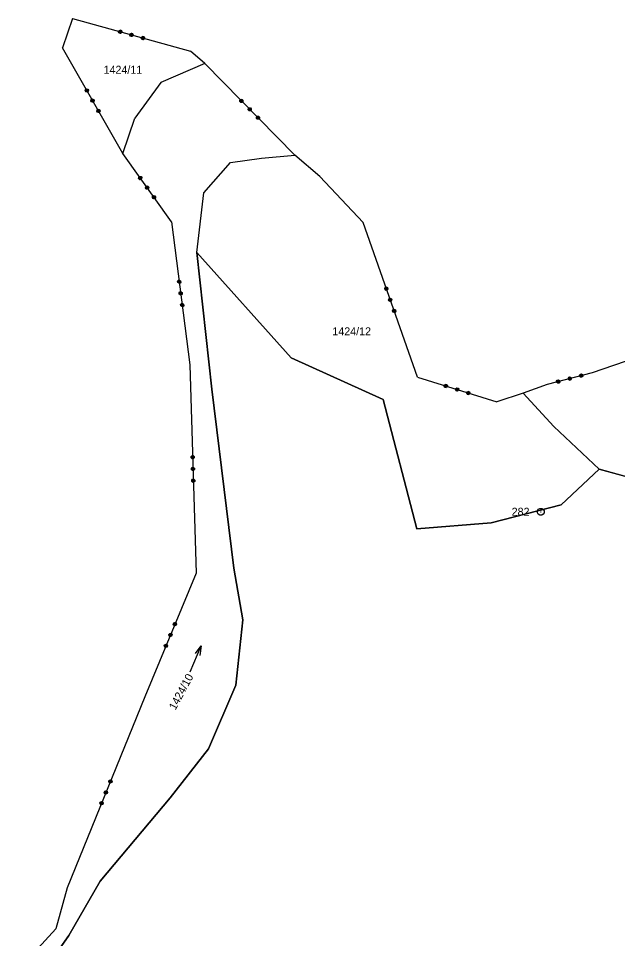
# Model space of a CAD drawing. Extents: x -779618 to -776429, y -1144546 to -1143350.
# Drawn here: x -779433.1 to -779305.8, y -1143589.4 to -1143393.9 of the extents above; entities that cross this region are included whole.
import ezdxf

# ---------------------------------------------------------------- set-up
doc = ezdxf.new("R2010")
doc.units = 0
for name, color, linetype in [('1', 7, 'Continuous'), ('11', 7, 'Continuous'), ('2', 7, 'Continuous'), ('3', 7, 'Continuous'), ('8', 7, 'Continuous')]:
    doc.layers.add(name, color=color, linetype=linetype)

msp = doc.modelspace()

# ---------------------------------------------------------------- linework, layer by layer
at = {"layer": '1'}
for p, q in [((-779421.62, -1143393.89), (-779423.77, -1143400.14)), ((-779421.62, -1143393.89), (-779396.57, -1143400.88)), ((-779410.98, -1143422.6), (-779423.77, -1143400.14)), ((-779393.56, -1143403.48), (-779396.57, -1143400.88)), ((-779393.56, -1143403.48), (-779402.9, -1143407.52)), ((-779393.56, -1143403.48), (-779374.42, -1143422.93)), ((-779402.9, -1143407.52), (-779408.4, -1143415.09)), ((-779410.98, -1143422.6), (-779408.4, -1143415.09)), ((-779400.61, -1143437.08), (-779410.98, -1143422.6)), ((-779381.5, -1143423.6), (-779374.42, -1143422.93)), ((-779369.08, -1143427.47), (-779374.42, -1143422.93)), ((-779393.75, -1143430.93), (-779388.05, -1143424.48)), ((-779388.05, -1143424.48), (-779381.5, -1143423.6)), ((-779359.9, -1143437.25), (-779369.08, -1143427.47)), ((-779395.24, -1143443.6), (-779393.75, -1143430.93)), ((-779400.61, -1143437.08), (-779396.69, -1143467.5)), ((-779348.37, -1143470.11), (-779359.9, -1143437.25)), ((-779375.19, -1143466.02), (-779395.24, -1143443.6)), ((-779395.24, -1143443.6), (-779392.06, -1143472.65)), ((-779396.69, -1143467.5), (-779395.39, -1143511.72)), ((-779355.63, -1143474.84), (-779375.19, -1143466.02)), ((-779301.92, -1143466.01), (-779311.23, -1143469.16)), ((-779311.23, -1143469.16), (-779320.76, -1143471.66)), ((-779348.37, -1143470.11), (-779331.49, -1143475.33)), ((-779320.76, -1143471.66), (-779325.89, -1143473.5)), ((-779392.06, -1143472.65), (-779387.33, -1143510.67)), ((-779325.89, -1143473.5), (-779331.49, -1143475.33)), ((-779319.39, -1143480.62), (-779325.89, -1143473.5)), ((-779348.5, -1143502.34), (-779355.63, -1143474.84)), ((-779309.71, -1143489.68), (-779319.39, -1143480.62)), ((-779309.71, -1143489.68), (-779317.8, -1143497.23)), ((-779287.14, -1143495.83), (-779309.71, -1143489.68)), ((-779317.8, -1143497.23), (-779332.68, -1143501.03)), ((-779332.68, -1143501.03), (-779348.5, -1143502.34)), ((-779387.33, -1143510.67), (-779385.43, -1143521.63)), ((-779395.39, -1143511.72), (-779406.26, -1143538.03)), ((-779385.43, -1143521.63), (-779386.97, -1143535.53)), ((-779386.97, -1143535.53), (-779392.76, -1143549.06)), ((-779406.26, -1143538.03), (-779422.8, -1143578.6)), ((-779392.76, -1143549.06), (-779400.9, -1143559.45)), ((-779400.9, -1143559.45), (-779415.75, -1143577.19)), ((-779415.75, -1143577.19), (-779422.4, -1143588.74)), ((-779422.8, -1143578.6), (-779425.2, -1143587.3)), ((-779425.2, -1143587.3), (-779441.4, -1143604.95)), ((-779422.4, -1143588.74), (-779431.16, -1143601.12))]:
    msp.add_line(p, q, dxfattribs=at)
for points in [[(-779411.29, -1143396.44), (-779411.16, -1143396.67), (-779411.23, -1143396.93), (-779411.47, -1143397.07), (-779411.73, -1143396.99), (-779411.86, -1143396.76), (-779411.79, -1143396.5), (-779411.55, -1143396.37), (-779411.29, -1143396.44), (-779411.29, -1143396.48), (-779411.52, -1143396.42), (-779411.62, -1143396.47), (-779411.24, -1143396.58), (-779411.2, -1143396.67), (-779411.72, -1143396.53), (-779411.74, -1143396.6), (-779411.23, -1143396.75), (-779411.24, -1143396.83), (-779411.75, -1143396.68), (-779411.78, -1143396.76), (-779411.27, -1143396.9), (-779411.34, -1143396.97), (-779411.75, -1143396.85), (-779411.7, -1143396.95), (-779411.43, -1143397.02)], [(-779408.87, -1143397.11), (-779408.74, -1143397.35), (-779408.81, -1143397.61), (-779409.05, -1143397.74), (-779409.31, -1143397.67), (-779409.44, -1143397.43), (-779409.37, -1143397.17), (-779409.13, -1143397.04), (-779408.87, -1143397.11), (-779408.89, -1143397.15), (-779409.13, -1143397.09), (-779409.22, -1143397.14), (-779408.84, -1143397.25), (-779408.78, -1143397.35), (-779409.32, -1143397.2), (-779409.34, -1143397.27), (-779408.8, -1143397.42), (-779408.83, -1143397.5), (-779409.37, -1143397.35), (-779409.39, -1143397.43), (-779408.85, -1143397.58), (-779408.95, -1143397.63), (-779409.33, -1143397.53), (-779409.28, -1143397.63), (-779409.05, -1143397.69)], [(-779406.46, -1143397.79), (-779406.32, -1143398.02), (-779406.4, -1143398.28), (-779406.63, -1143398.42), (-779406.89, -1143398.34), (-779407.02, -1143398.11), (-779406.95, -1143397.85), (-779406.72, -1143397.72), (-779406.46, -1143397.79), (-779406.51, -1143397.82), (-779406.74, -1143397.75), (-779406.82, -1143397.81), (-779406.45, -1143397.92), (-779406.39, -1143398.01), (-779406.9, -1143397.87), (-779406.92, -1143397.95), (-779406.42, -1143398.09), (-779406.44, -1143398.17), (-779406.94, -1143398.03), (-779406.97, -1143398.1), (-779406.47, -1143398.24), (-779406.53, -1143398.31), (-779406.92, -1143398.2), (-779406.9, -1143398.29), (-779406.67, -1143398.35)], [(-779418.96, -1143409.22), (-779418.89, -1143408.97), (-779418.66, -1143408.83), (-779418.4, -1143408.9), (-779418.26, -1143409.14), (-779418.34, -1143409.4), (-779418.57, -1143409.53), (-779418.83, -1143409.46), (-779418.96, -1143409.22), (-779418.91, -1143409.24), (-779418.79, -1143409.45), (-779418.69, -1143409.46), (-779418.88, -1143409.13), (-779418.85, -1143409.02), (-779418.59, -1143409.47), (-779418.52, -1143409.43), (-779418.78, -1143408.98), (-779418.71, -1143408.94), (-779418.45, -1143409.39), (-779418.38, -1143409.36), (-779418.64, -1143408.91), (-779418.55, -1143408.91), (-779418.34, -1143409.26), (-779418.3, -1143409.18), (-779418.42, -1143408.97)], [(-779417.72, -1143411.41), (-779417.65, -1143411.15), (-779417.42, -1143411.01), (-779417.16, -1143411.09), (-779417.02, -1143411.32), (-779417.1, -1143411.58), (-779417.33, -1143411.71), (-779417.59, -1143411.64), (-779417.72, -1143411.41), (-779417.68, -1143411.4), (-779417.56, -1143411.6), (-779417.45, -1143411.63), (-779417.65, -1143411.29), (-779417.62, -1143411.18), (-779417.35, -1143411.66), (-779417.28, -1143411.62), (-779417.55, -1143411.14), (-779417.48, -1143411.1), (-779417.21, -1143411.58), (-779417.14, -1143411.55), (-779417.41, -1143411.06), (-779417.3, -1143411.09), (-779417.11, -1143411.44), (-779417.08, -1143411.33), (-779417.2, -1143411.12)], [(-779385.42, -1143411.29), (-779385.43, -1143411.56), (-779385.62, -1143411.75), (-779385.89, -1143411.75), (-779386.08, -1143411.56), (-779386.08, -1143411.29), (-779385.88, -1143411.1), (-779385.61, -1143411.1), (-779385.42, -1143411.29), (-779385.45, -1143411.33), (-779385.61, -1143411.16), (-779385.73, -1143411.15), (-779385.45, -1143411.44), (-779385.46, -1143411.54), (-779385.84, -1143411.15), (-779385.9, -1143411.21), (-779385.53, -1143411.59), (-779385.58, -1143411.65), (-779385.95, -1143411.27), (-779386, -1143411.33), (-779385.63, -1143411.71), (-779385.73, -1143411.73), (-779386.03, -1143411.42), (-779386.03, -1143411.53), (-779385.84, -1143411.73)], [(-779383.66, -1143413.08), (-779383.67, -1143413.35), (-779383.86, -1143413.54), (-779384.13, -1143413.54), (-779384.32, -1143413.34), (-779384.31, -1143413.08), (-779384.12, -1143412.89), (-779383.85, -1143412.89), (-779383.66, -1143413.08), (-779383.7, -1143413.1), (-779383.87, -1143412.93), (-779383.98, -1143412.93), (-779383.7, -1143413.21), (-779383.7, -1143413.33), (-779384.09, -1143412.93), (-779384.15, -1143412.98), (-779383.76, -1143413.38), (-779383.82, -1143413.44), (-779384.21, -1143413.04), (-779384.26, -1143413.1), (-779383.87, -1143413.5), (-779383.99, -1143413.49), (-779384.27, -1143413.21), (-779384.27, -1143413.32), (-779384.1, -1143413.49)], [(-779416.48, -1143413.59), (-779416.41, -1143413.33), (-779416.18, -1143413.2), (-779415.92, -1143413.27), (-779415.78, -1143413.5), (-779415.85, -1143413.76), (-779416.09, -1143413.89), (-779416.35, -1143413.82), (-779416.48, -1143413.59), (-779416.45, -1143413.56), (-779416.33, -1143413.77), (-779416.22, -1143413.8), (-779416.42, -1143413.45), (-779416.38, -1143413.36), (-779416.11, -1143413.83), (-779416.05, -1143413.79), (-779416.31, -1143413.33), (-779416.24, -1143413.28), (-779415.98, -1143413.74), (-779415.91, -1143413.7), (-779416.17, -1143413.24), (-779416.08, -1143413.24), (-779415.87, -1143413.62), (-779415.83, -1143413.52), (-779415.97, -1143413.27)], [(-779381.9, -1143414.87), (-779381.9, -1143415.14), (-779382.1, -1143415.33), (-779382.37, -1143415.32), (-779382.56, -1143415.13), (-779382.55, -1143414.86), (-779382.36, -1143414.67), (-779382.09, -1143414.68), (-779381.9, -1143414.87), (-779381.96, -1143414.87), (-779382.13, -1143414.7), (-779382.23, -1143414.71), (-779381.96, -1143414.98), (-779381.96, -1143415.09), (-779382.33, -1143414.72), (-779382.38, -1143414.78), (-779382.02, -1143415.15), (-779382.08, -1143415.21), (-779382.44, -1143414.84), (-779382.5, -1143414.89), (-779382.14, -1143415.26), (-779382.22, -1143415.28), (-779382.51, -1143414.99), (-779382.53, -1143415.08), (-779382.37, -1143415.25)], [(-779407.6, -1143427.87), (-779407.55, -1143427.61), (-779407.33, -1143427.45), (-779407.07, -1143427.49), (-779406.91, -1143427.71), (-779406.96, -1143427.98), (-779407.18, -1143428.13), (-779407.44, -1143428.09), (-779407.6, -1143427.87), (-779407.54, -1143427.88), (-779407.4, -1143428.08), (-779407.3, -1143428.08), (-779407.52, -1143427.77), (-779407.5, -1143427.66), (-779407.2, -1143428.08), (-779407.14, -1143428.03), (-779407.44, -1143427.61), (-779407.37, -1143427.56), (-779407.07, -1143427.99), (-779407, -1143427.95), (-779407.3, -1143427.53), (-779407.22, -1143427.51), (-779406.98, -1143427.85), (-779406.94, -1143427.76), (-779407.08, -1143427.56)], [(-779406.14, -1143429.91), (-779406.09, -1143429.65), (-779405.87, -1143429.49), (-779405.61, -1143429.53), (-779405.45, -1143429.75), (-779405.49, -1143430.02), (-779405.71, -1143430.18), (-779405.98, -1143430.13), (-779406.14, -1143429.91), (-779406.1, -1143429.9), (-779405.96, -1143430.09), (-779405.85, -1143430.11), (-779406.08, -1143429.79), (-779406.06, -1143429.67), (-779405.74, -1143430.13), (-779405.67, -1143430.08), (-779406, -1143429.63), (-779405.93, -1143429.58), (-779405.61, -1143430.04), (-779405.54, -1143429.99), (-779405.87, -1143429.53), (-779405.75, -1143429.55), (-779405.52, -1143429.88), (-779405.5, -1143429.77), (-779405.64, -1143429.57)], [(-779404.68, -1143431.95), (-779404.63, -1143431.69), (-779404.41, -1143431.53), (-779404.15, -1143431.58), (-779403.99, -1143431.79), (-779404.03, -1143432.06), (-779404.25, -1143432.22), (-779404.52, -1143432.17), (-779404.68, -1143431.95), (-779404.65, -1143431.92), (-779404.51, -1143432.12), (-779404.4, -1143432.14), (-779404.63, -1143431.81), (-779404.6, -1143431.72), (-779404.29, -1143432.15), (-779404.22, -1143432.11), (-779404.53, -1143431.68), (-779404.47, -1143431.62), (-779404.16, -1143432.05), (-779404.1, -1143432.01), (-779404.41, -1143431.58), (-779404.31, -1143431.57), (-779404.06, -1143431.92), (-779404.04, -1143431.82), (-779404.2, -1143431.59)], [(-779398.64, -1143449.9), (-779398.8, -1143450.11), (-779399.07, -1143450.15), (-779399.28, -1143449.98), (-779399.32, -1143449.71), (-779399.15, -1143449.5), (-779398.88, -1143449.47), (-779398.67, -1143449.63), (-779398.64, -1143449.9), (-779398.67, -1143449.91), (-779398.71, -1143449.68), (-779398.8, -1143449.61), (-779398.74, -1143450), (-779398.82, -1143450.07), (-779398.88, -1143449.54), (-779398.96, -1143449.55), (-779398.9, -1143450.07), (-779398.97, -1143450.09), (-779399.04, -1143449.57), (-779399.12, -1143449.58), (-779399.05, -1143450.1), (-779399.14, -1143450.06), (-779399.19, -1143449.64), (-779399.27, -1143449.72), (-779399.23, -1143450)], [(-779398.31, -1143452.39), (-779398.48, -1143452.6), (-779398.75, -1143452.64), (-779398.96, -1143452.47), (-779398.99, -1143452.2), (-779398.83, -1143451.99), (-779398.56, -1143451.96), (-779398.35, -1143452.12), (-779398.31, -1143452.39), (-779398.36, -1143452.38), (-779398.39, -1143452.14), (-779398.48, -1143452.08), (-779398.42, -1143452.47), (-779398.49, -1143452.56), (-779398.57, -1143452.01), (-779398.64, -1143452.02), (-779398.57, -1143452.57), (-779398.65, -1143452.58), (-779398.72, -1143452.03), (-779398.8, -1143452.04), (-779398.73, -1143452.59), (-779398.82, -1143452.52), (-779398.87, -1143452.13), (-779398.94, -1143452.22), (-779398.91, -1143452.45)], [(-779355.31, -1143451.29), (-779355.2, -1143451.04), (-779354.94, -1143450.95), (-779354.7, -1143451.07), (-779354.61, -1143451.32), (-779354.73, -1143451.57), (-779354.98, -1143451.66), (-779355.22, -1143451.54), (-779355.31, -1143451.29), (-779355.26, -1143451.31), (-779355.18, -1143451.54), (-779355.09, -1143451.57), (-779355.21, -1143451.21), (-779355.16, -1143451.11), (-779354.99, -1143451.6), (-779354.92, -1143451.57), (-779355.09, -1143451.08), (-779355.01, -1143451.05), (-779354.84, -1143451.54), (-779354.76, -1143451.53), (-779354.93, -1143451.04), (-779354.85, -1143451.05), (-779354.71, -1143451.43), (-779354.65, -1143451.36), (-779354.73, -1143451.13)], [(-779354.48, -1143453.65), (-779354.37, -1143453.41), (-779354.11, -1143453.32), (-779353.87, -1143453.44), (-779353.78, -1143453.69), (-779353.9, -1143453.94), (-779354.15, -1143454.02), (-779354.39, -1143453.91), (-779354.48, -1143453.65), (-779354.44, -1143453.65), (-779354.36, -1143453.88), (-779354.26, -1143453.93), (-779354.39, -1143453.55), (-779354.34, -1143453.45), (-779354.16, -1143453.97), (-779354.08, -1143453.95), (-779354.27, -1143453.42), (-779354.19, -1143453.39), (-779354.01, -1143453.92), (-779353.93, -1143453.9), (-779354.12, -1143453.37), (-779354.02, -1143453.42), (-779353.88, -1143453.79), (-779353.83, -1143453.69), (-779353.91, -1143453.46)], [(-779397.99, -1143454.88), (-779398.16, -1143455.09), (-779398.42, -1143455.12), (-779398.64, -1143454.96), (-779398.67, -1143454.69), (-779398.51, -1143454.48), (-779398.24, -1143454.45), (-779398.03, -1143454.61), (-779397.99, -1143454.88), (-779398.04, -1143454.84), (-779398.07, -1143454.6), (-779398.16, -1143454.56), (-779398.11, -1143454.93), (-779398.18, -1143455.02), (-779398.24, -1143454.51), (-779398.32, -1143454.52), (-779398.26, -1143455.03), (-779398.33, -1143455.04), (-779398.4, -1143454.53), (-779398.48, -1143454.53), (-779398.42, -1143455.04), (-779398.5, -1143455.01), (-779398.55, -1143454.61), (-779398.63, -1143454.67), (-779398.59, -1143454.9)], [(-779353.65, -1143456.02), (-779353.54, -1143455.78), (-779353.28, -1143455.69), (-779353.04, -1143455.81), (-779352.95, -1143456.06), (-779353.07, -1143456.3), (-779353.32, -1143456.39), (-779353.56, -1143456.28), (-779353.65, -1143456.02), (-779353.62, -1143456), (-779353.54, -1143456.23), (-779353.44, -1143456.28), (-779353.57, -1143455.9), (-779353.51, -1143455.81), (-779353.34, -1143456.32), (-779353.26, -1143456.3), (-779353.43, -1143455.8), (-779353.36, -1143455.76), (-779353.19, -1143456.26), (-779353.11, -1143456.24), (-779353.29, -1143455.74), (-779353.2, -1143455.76), (-779353.05, -1143456.16), (-779353, -1143456.07), (-779353.09, -1143455.81)], [(-779313.62, -1143470.12), (-779313.85, -1143469.98), (-779313.92, -1143469.72), (-779313.79, -1143469.49), (-779313.52, -1143469.42), (-779313.29, -1143469.56), (-779313.22, -1143469.82), (-779313.36, -1143470.05), (-779313.62, -1143470.12), (-779313.64, -1143470.08), (-779313.41, -1143470.02), (-779313.35, -1143469.92), (-779313.74, -1143470.03), (-779313.82, -1143469.96), (-779313.29, -1143469.83), (-779313.32, -1143469.75), (-779313.83, -1143469.88), (-779313.86, -1143469.81), (-779313.35, -1143469.67), (-779313.37, -1143469.6), (-779313.88, -1143469.73), (-779313.85, -1143469.64), (-779313.43, -1143469.53), (-779313.52, -1143469.47), (-779313.79, -1143469.54)], [(-779342.1, -1143471.71), (-779341.97, -1143471.95), (-779342.05, -1143472.21), (-779342.29, -1143472.33), (-779342.55, -1143472.25), (-779342.67, -1143472.02), (-779342.6, -1143471.76), (-779342.36, -1143471.63), (-779342.1, -1143471.71), (-779342.1, -1143471.75), (-779342.33, -1143471.68), (-779342.43, -1143471.74), (-779342.05, -1143471.85), (-779342.02, -1143471.95), (-779342.53, -1143471.79), (-779342.55, -1143471.87), (-779342.05, -1143472.02), (-779342.06, -1143472.1), (-779342.57, -1143471.95), (-779342.59, -1143472.02), (-779342.09, -1143472.18), (-779342.16, -1143472.24), (-779342.57, -1143472.11), (-779342.53, -1143472.21), (-779342.26, -1143472.29)], [(-779318.48, -1143471.39), (-779318.71, -1143471.26), (-779318.78, -1143470.99), (-779318.64, -1143470.76), (-779318.38, -1143470.69), (-779318.15, -1143470.83), (-779318.08, -1143471.09), (-779318.22, -1143471.32), (-779318.48, -1143471.39), (-779318.45, -1143471.34), (-779318.22, -1143471.28), (-779318.18, -1143471.19), (-779318.55, -1143471.29), (-779318.64, -1143471.23), (-779318.14, -1143471.1), (-779318.16, -1143471.02), (-779318.66, -1143471.15), (-779318.68, -1143471.07), (-779318.18, -1143470.94), (-779318.19, -1143470.86), (-779318.7, -1143470.99), (-779318.68, -1143470.91), (-779318.28, -1143470.8), (-779318.35, -1143470.74), (-779318.58, -1143470.8)], [(-779316.05, -1143470.76), (-779316.28, -1143470.62), (-779316.35, -1143470.36), (-779316.21, -1143470.13), (-779315.95, -1143470.06), (-779315.72, -1143470.19), (-779315.65, -1143470.45), (-779315.79, -1143470.69), (-779316.05, -1143470.76), (-779316.05, -1143470.71), (-779315.82, -1143470.65), (-779315.76, -1143470.56), (-779316.15, -1143470.66), (-779316.25, -1143470.6), (-779315.7, -1143470.46), (-779315.72, -1143470.38), (-779316.27, -1143470.52), (-779316.29, -1143470.44), (-779315.74, -1143470.3), (-779315.76, -1143470.23), (-779316.31, -1143470.37), (-779316.25, -1143470.27), (-779315.86, -1143470.17), (-779315.96, -1143470.11), (-779316.19, -1143470.17)], [(-779339.7, -1143472.46), (-779339.58, -1143472.69), (-779339.66, -1143472.95), (-779339.89, -1143473.08), (-779340.15, -1143473), (-779340.28, -1143472.76), (-779340.2, -1143472.5), (-779339.96, -1143472.38), (-779339.7, -1143472.46), (-779339.72, -1143472.49), (-779339.95, -1143472.42), (-779340.05, -1143472.47), (-779339.67, -1143472.59), (-779339.62, -1143472.69), (-779340.15, -1143472.53), (-779340.18, -1143472.6), (-779339.64, -1143472.77), (-779339.66, -1143472.84), (-779340.2, -1143472.68), (-779340.22, -1143472.75), (-779339.69, -1143472.92), (-779339.79, -1143472.97), (-779340.17, -1143472.85), (-779340.12, -1143472.95), (-779339.89, -1143473.03)], [(-779337.3, -1143473.2), (-779337.18, -1143473.44), (-779337.26, -1143473.69), (-779337.5, -1143473.82), (-779337.75, -1143473.74), (-779337.88, -1143473.5), (-779337.8, -1143473.24), (-779337.56, -1143473.12), (-779337.3, -1143473.2), (-779337.35, -1143473.22), (-779337.58, -1143473.15), (-779337.66, -1143473.21), (-779337.3, -1143473.32), (-779337.25, -1143473.42), (-779337.75, -1143473.27), (-779337.77, -1143473.35), (-779337.27, -1143473.5), (-779337.3, -1143473.58), (-779337.79, -1143473.42), (-779337.83, -1143473.5), (-779337.33, -1143473.65), (-779337.39, -1143473.72), (-779337.78, -1143473.59), (-779337.76, -1143473.69), (-779337.53, -1143473.76)], [(-779395.79, -1143487.23), (-779395.97, -1143487.43), (-779396.24, -1143487.44), (-779396.44, -1143487.25), (-779396.45, -1143486.98), (-779396.26, -1143486.79), (-779395.99, -1143486.78), (-779395.8, -1143486.96), (-779395.79, -1143487.23), (-779395.83, -1143487.24), (-779395.84, -1143487), (-779395.92, -1143486.93), (-779395.91, -1143487.33), (-779395.99, -1143487.39), (-779396, -1143486.85), (-779396.08, -1143486.85), (-779396.07, -1143487.38), (-779396.15, -1143487.39), (-779396.16, -1143486.86), (-779396.24, -1143486.86), (-779396.23, -1143487.39), (-779396.31, -1143487.35), (-779396.32, -1143486.92), (-779396.4, -1143486.99), (-779396.39, -1143487.27)], [(-779395.72, -1143489.74), (-779395.9, -1143489.94), (-779396.17, -1143489.94), (-779396.37, -1143489.76), (-779396.37, -1143489.49), (-779396.19, -1143489.29), (-779395.92, -1143489.29), (-779395.72, -1143489.47), (-779395.72, -1143489.74), (-779395.76, -1143489.73), (-779395.76, -1143489.49), (-779395.85, -1143489.41), (-779395.83, -1143489.81), (-779395.91, -1143489.9), (-779395.93, -1143489.34), (-779396.01, -1143489.34), (-779395.99, -1143489.9), (-779396.07, -1143489.9), (-779396.09, -1143489.34), (-779396.17, -1143489.34), (-779396.15, -1143489.9), (-779396.23, -1143489.83), (-779396.25, -1143489.43), (-779396.32, -1143489.51), (-779396.32, -1143489.75)], [(-779395.64, -1143492.25), (-779395.83, -1143492.44), (-779396.1, -1143492.45), (-779396.29, -1143492.27), (-779396.3, -1143492), (-779396.12, -1143491.8), (-779395.85, -1143491.8), (-779395.65, -1143491.98), (-779395.64, -1143492.25), (-779395.68, -1143492.21), (-779395.69, -1143491.97), (-779395.77, -1143491.91), (-779395.76, -1143492.29), (-779395.84, -1143492.38), (-779395.85, -1143491.86), (-779395.93, -1143491.86), (-779395.92, -1143492.38), (-779396, -1143492.38), (-779396.01, -1143491.86), (-779396.09, -1143491.85), (-779396.08, -1143492.37), (-779396.16, -1143492.33), (-779396.17, -1143491.92), (-779396.25, -1143491.98), (-779396.24, -1143492.22)], [(-779399.63, -1143522.81), (-779399.87, -1143522.91), (-779400.12, -1143522.81), (-779400.23, -1143522.56), (-779400.12, -1143522.31), (-779399.87, -1143522.21), (-779399.63, -1143522.31), (-779399.52, -1143522.56), (-779399.63, -1143522.81), (-779399.67, -1143522.8), (-779399.57, -1143522.58), (-779399.62, -1143522.47), (-779399.77, -1143522.84), (-779399.87, -1143522.87), (-779399.66, -1143522.37), (-779399.74, -1143522.34), (-779399.94, -1143522.83), (-779400.02, -1143522.81), (-779399.81, -1143522.32), (-779399.89, -1143522.29), (-779400.09, -1143522.78), (-779400.14, -1143522.7), (-779399.98, -1143522.3), (-779400.08, -1143522.34), (-779400.19, -1143522.6)], [(-779400.58, -1143525.13), (-779400.83, -1143525.23), (-779401.08, -1143525.13), (-779401.18, -1143524.88), (-779401.08, -1143524.63), (-779400.83, -1143524.53), (-779400.58, -1143524.63), (-779400.48, -1143524.88), (-779400.58, -1143525.13), (-779400.62, -1143525.1), (-779400.52, -1143524.88), (-779400.57, -1143524.78), (-779400.72, -1143525.15), (-779400.82, -1143525.19), (-779400.61, -1143524.67), (-779400.69, -1143524.64), (-779400.9, -1143525.16), (-779400.97, -1143525.13), (-779400.76, -1143524.61), (-779400.83, -1143524.58), (-779401.05, -1143525.1), (-779401.09, -1143524.99), (-779400.94, -1143524.62), (-779401.04, -1143524.67), (-779401.13, -1143524.89)], [(-779401.54, -1143527.45), (-779401.79, -1143527.55), (-779402.04, -1143527.45), (-779402.14, -1143527.2), (-779402.04, -1143526.95), (-779401.79, -1143526.85), (-779401.54, -1143526.95), (-779401.44, -1143527.2), (-779401.54, -1143527.45), (-779401.56, -1143527.39), (-779401.47, -1143527.17), (-779401.52, -1143527.09), (-779401.67, -1143527.44), (-779401.77, -1143527.48), (-779401.57, -1143527), (-779401.65, -1143526.97), (-779401.84, -1143527.45), (-779401.92, -1143527.42), (-779401.72, -1143526.94), (-779401.79, -1143526.9), (-779401.99, -1143527.38), (-779402.05, -1143527.31), (-779401.89, -1143526.93), (-779401.98, -1143526.95), (-779402.08, -1143527.17)], [(-779413.34, -1143556.24), (-779413.59, -1143556.35), (-779413.84, -1143556.24), (-779413.94, -1143556), (-779413.84, -1143555.75), (-779413.59, -1143555.64), (-779413.34, -1143555.74), (-779413.24, -1143555.99), (-779413.34, -1143556.24), (-779413.38, -1143556.24), (-779413.29, -1143556.01), (-779413.33, -1143555.91), (-779413.48, -1143556.28), (-779413.58, -1143556.3), (-779413.38, -1143555.8), (-779413.45, -1143555.77), (-779413.65, -1143556.27), (-779413.73, -1143556.24), (-779413.53, -1143555.75), (-779413.6, -1143555.72), (-779413.8, -1143556.21), (-779413.86, -1143556.14), (-779413.7, -1143555.74), (-779413.8, -1143555.77), (-779413.9, -1143556.03)], [(-779414.29, -1143558.57), (-779414.53, -1143558.67), (-779414.78, -1143558.57), (-779414.89, -1143558.32), (-779414.79, -1143558.07), (-779414.54, -1143557.97), (-779414.29, -1143558.07), (-779414.18, -1143558.32), (-779414.29, -1143558.57), (-779414.32, -1143558.54), (-779414.23, -1143558.32), (-779414.27, -1143558.21), (-779414.42, -1143558.58), (-779414.53, -1143558.63), (-779414.32, -1143558.11), (-779414.39, -1143558.08), (-779414.6, -1143558.6), (-779414.68, -1143558.57), (-779414.47, -1143558.05), (-779414.54, -1143558.02), (-779414.75, -1143558.54), (-779414.79, -1143558.43), (-779414.64, -1143558.06), (-779414.75, -1143558.11), (-779414.84, -1143558.33)], [(-779415.23, -1143560.89), (-779415.48, -1143560.99), (-779415.73, -1143560.89), (-779415.84, -1143560.64), (-779415.73, -1143560.39), (-779415.49, -1143560.29), (-779415.24, -1143560.39), (-779415.13, -1143560.64), (-779415.23, -1143560.89), (-779415.26, -1143560.84), (-779415.17, -1143560.62), (-779415.22, -1143560.53), (-779415.36, -1143560.88), (-779415.47, -1143560.93), (-779415.27, -1143560.44), (-779415.34, -1143560.41), (-779415.54, -1143560.89), (-779415.61, -1143560.86), (-779415.42, -1143560.38), (-779415.49, -1143560.34), (-779415.68, -1143560.83), (-779415.74, -1143560.76), (-779415.59, -1143560.38), (-779415.68, -1143560.39), (-779415.77, -1143560.62)]]:
    msp.add_lwpolyline(points, dxfattribs=at)
at = {"layer": '11'}
msp.add_lwpolyline([(-779504, -1143647.17), (-779493.22, -1143647.23), (-779479.43, -1143644.1), (-779468.43, -1143638.83), (-779458.09, -1143632.15), (-779448.47, -1143623.31), (-779437.37, -1143611.48), (-779431.16, -1143601.12), (-779422.4, -1143588.74), (-779415.75, -1143577.19), (-779400.9, -1143559.45), (-779392.76, -1143549.06), (-779386.97, -1143535.53), (-779385.43, -1143521.63), (-779387.33, -1143510.67), (-779392.06, -1143472.65), (-779395.24, -1143443.6), (-779375.19, -1143466.02), (-779355.63, -1143474.84), (-779348.5, -1143502.34), (-779332.68, -1143501.03), (-779317.8, -1143497.23), (-779309.71, -1143489.68), (-779287.14, -1143495.83)], dxfattribs=at)
at = {"layer": '3'}
msp.add_line((-779396.62, -1143532.7), (-779394.3, -1143527.18), dxfattribs=at)
msp.add_lwpolyline([(-779395.53, -1143528.82), (-779394.3, -1143527.18), (-779394.61, -1143529.21)], dxfattribs=at)
at = {"layer": '8'}
msp.add_line((-779322.18, -1143498.7), (-779322.08, -1143498.7), dxfattribs=at)
msp.add_lwpolyline([(-779321.94, -1143497.98), (-779321.6, -1143498.17), (-779321.41, -1143498.51), (-779321.41, -1143498.9), (-779321.6, -1143499.24), (-779321.94, -1143499.43), (-779322.33, -1143499.43), (-779322.67, -1143499.24), (-779322.86, -1143498.9), (-779322.86, -1143498.51), (-779322.67, -1143498.17), (-779322.33, -1143497.98)], close=True, dxfattribs=at)

# ---------------------------------------------------------------- texts
at = {"layer": '2'}
for s, p in [('1424/11', (-779415.04, -1143405.65)), ('1424/12', (-779366.43, -1143461.22))]:
    msp.add_text(s, height=1.7, dxfattribs=at).set_placement(p)
msp.add_text('1424/10', height=1.7, rotation=61.7649, dxfattribs=at).set_placement((-779399.77, -1143540.95))
at = {"layer": '8'}
msp.add_text('282', height=1.7, dxfattribs=at).set_placement((-779328.33, -1143499.55))

doc.saveas('drawing.dxf')
